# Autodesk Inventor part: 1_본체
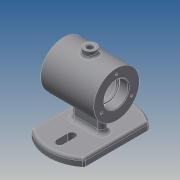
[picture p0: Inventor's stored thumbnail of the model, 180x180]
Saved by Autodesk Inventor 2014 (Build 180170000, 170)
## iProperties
Created: 2017-12
Part Number: 1_본체
Material: Generic
Document SubType Name: Modeling
Designer: kb542-24
Density: 1 g/cm^3
Appearance: Default
Mass: 172.58 g
Surface Area: 486.488 cm^2
Volume: 172.58 cm^3
Author: kb542-24
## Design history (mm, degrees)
sketch "스케치1"
  geometry: L1 (-35, 0)-(35, 0); L2 (-20, 14)-(-23, 14); L3 (-23, 14)-(-23, 16); L4 (-23, 16)-(-35, 16); L5 (-35, 16)-(-35, 30); L6 (-35, 30)-(35, 30); L7 (35, 30)-(35, 16); L8 (35, 16)-(23, 16); L9 (23, 16)-(23, 14); L10 (23, 14)-(20, 14); L11 (20, 14)-(20, 25); L12 (20, 25)-(-20, 25); L13 (-20, 25)-(-20, 14); 2 further points
  constraints: 26 end point, 8 parallel, 2 horizontal, 2 vertical alignment, 1 coincident, 1 collinear, 1 midpoint, 1 perpendicular, 1 vertical
  dimensions: "d0" = 70 distance of L5.end L6.end; "d1" = 32 diameter of L4 L1; "d2" = 32 diameter of L8 L1; "d3" = 12 distance of L3.end L4.end; "d4" = 12 distance of L7.end L8.end; "d5" = 40 distance of L11.end L12.end; "d6" = 50 diameter of L12 L1; "d7" = 3 distance of L9.end L10.end; "d8" = 28 diameter of L2 L1; "d9" = 28 diameter of L10 L1; "d10" = 60 diameter of L6 L1
revolve "회전1" sketch "스케치1" stored, may be unused: angle "d11" = 90 deg
node "작업 평면1"
sketch "스케치2"
  geometry: L1 (-35, 42.426)-(35, 42.426); L2 (35, 42.426)-(35, -42.426); L3 (-35, 42.426)-(-35, -42.426); L4 (-35, -42.426)-(35, -42.426); A1 r 55 centre (0, 0) between (-35, -42.426) and (35, -42.426); A2 r 55 centre (0, 0) between (35, 42.426) and (-35, 42.426); 1 further point
  constraints: 8 end point, 4 point on circle, 2 centre point, 2 perpendicular, 1 coincident, 1 horizontal, 1 parallel
  dimensions: "d14" = 70 distance of L1.start L1.end; "d15" = 110 diameter of A1; "d17" = 110 diameter of A2
extrude "돌출1" join sketch "스케치2" distance "d18" = 10; taper "d19" = 0 deg
sketch "스케치3"
  geometry: L1 (-35, 42.426)-(-35, -42.426) reference; L2 (35, -42.426)-(35, 42.426) reference; L3 (0, 40)-(0, 24); L4 (5, 40)-(5, 24); L5 (-5, 24)-(-5, 40); L6 (-35, 0)-(35, 0); L7 (0, -40)-(0, -24); L8 (5, -40)-(5, -24); L9 (-5, -24)-(-5, -40); A1 r 55 centre (0, 0) between (-35, -42.426) and (35, -42.426) reference; A2 r 5 centre (0, 40) between (5, 40) and (-5, 40); A3 r 5 centre (0, 24) between (-5, 24) and (5, 24); A4 r 5 centre (0, -40) between (-5, -40) and (5, -40); A5 r 5 centre (0, -24) between (5, -24) and (-5, -24); 2 further points
  constraints: 18 end point, 8 point on circle, 7 symmetric about line, 4 centre point, 4 tangent, 3 midpoint, 2 parallel, 1 vertical alignment, 2 other
  dimensions: "d20" = 5 radius of A2; "d21" = 24 distance of L3.end A1.centre; "d22" = 16 distance of L3.end L3.start
extrude "돌출2" cut sketch "스케치3" distance "d23" = 10; taper "d24" = 0 deg
sketch "스케치4"
  geometry: L1 (35, -42.426)-(35, 42.426) reference; L2 (15, 0)-(-15, 0); L3 (15, -5)-(-15, -5); L4 (-15, 5)-(15, 5); A1 r 55 centre (0, 0) between (35, 42.426) and (-35, 42.426) reference; A2 r 5 centre (15, 0) between (15, -5) and (15, 5); A3 r 5 centre (-15, 0) between (-15, 5) and (-15, -5)
  constraints: 8 end point, 4 point on circle, 4 tangent, 2 centre point, 1 midpoint, 1 parallel, 1 perpendicular
  dimensions: "d25" = 5 radius of A3; "d26" = 30 distance of L2.start L2.end
extrude "돌출3" join sketch "스케치4" stored distance "d27" = 10; taper "d28" = 0 deg
fillet "모깎기1" dims "d29" = 5
sketch "스케치5"
  geometry: C1 r 16 at (0, 0) reference; 1 further point
  constraints: 1 horizontal alignment
  dimensions: "d30" = 23 distance of C1.centre point (-23, 0)
hole "구멍1" sketch "스케치5" at (-23, 0) diameter "d31" = 3.242; stored, may be unused: countersink angle "d35" = 90 deg, drill point angle "d37" = 118 deg; dims "d32" = 8, "d33" = 4, "d34" = 2, "d36" = 10
node "작업 평면2"
sketch "스케치7"
  geometry: L1 (-35, -30)-(-35, 30) reference; C1 r 8 at (0, 0); 1 further point
  constraints: 1 centre point, 1 coincident
  dimensions: "d42" = 35 distance from line of C1.centre L1; "d43" = 16 diameter of C1
extrude "돌출4" join sketch "스케치7" stored distance "d44" = 10; taper "d45" = 0 deg
sketch "스케치8"
  geometry: C1 r 8 at (0, 0) reference; C2 r 4 at (0, 0)
  constraints: 1 centre point, 1 coincident
  dimensions: "d46" = 8 diameter of C2
extrude "돌출5" cut sketch "스케치8" stored distance "d47" = 10; taper "d48" = 0 deg
node "작업 평면3"
sketch "스케치9"
  geometry: L1 (-35, 30)-(-35, -30) reference; L2 (35, 30)-(-35, 30) reference; 2 further points
  constraints: 1 other
  dimensions: "d49" = 35 distance from line of point (0, 0) L1; "d50" = 30 distance from line of point (0, 0) L2
feature "엠보싱1" sketch "스케치9" dims "d0" = 70, "d1" = 32, "d2" = 32, "d3" = 12, "d4" = 12, "d5" = 40, "d6" = 50, "d7" = 3, "d8" = 28, "d9" = 28, "d10" = 60, "d14" = 70, "d15" = 110, "d17" = 110, "d51" = 0.5, "d52" = 0
fillet "모깎기2" dims "d53" = 0.3
fillet "모깎기3" dims "d54" = 3
chamfer "모따기1" distance "d55" = 1; stored, may be unused: second distance "d56" = 2, angle "d57" = 45 deg
chamfer "모따기2" distance "d58" = 1; stored, may be unused: second distance "d59" = 2, angle "d60" = 45 deg
fillet "모깎기4" dims "d61" = 3
fillet "모깎기5" dims "d62" = 3
fillet "모깎기6" dims "d63" = 3
node "솔리드1"
pattern_circular "원형 패턴1" dims angle "d39" = 360 deg
mirror "대칭1"
other parameters: "d12" = -62, "d41" = 37
